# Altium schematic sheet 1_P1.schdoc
size 307 x 218 mm; Symbol: Drawing-Symbol_A4; Device: Drawing-Symbol_A4; @Project Name: Pixeldust-dr; @Page Count: 1; @Update Date: 2025-04-12; @Create Date: 2025-04-03; @Schematic Name: Schematic1; @Page No: 1; @Page Name: P1; Company: EasyEDA.com; Version: V1.0; Page Size: A4; @Create Time: 14:28:44; @Update Time: 18:55:47; Width: 1170; Height: 825; Region Start: 1; X Region Count: 6; Y Region Count: 4; Blade Width: 10; Title Block Position: 3; @Board Name: Board1
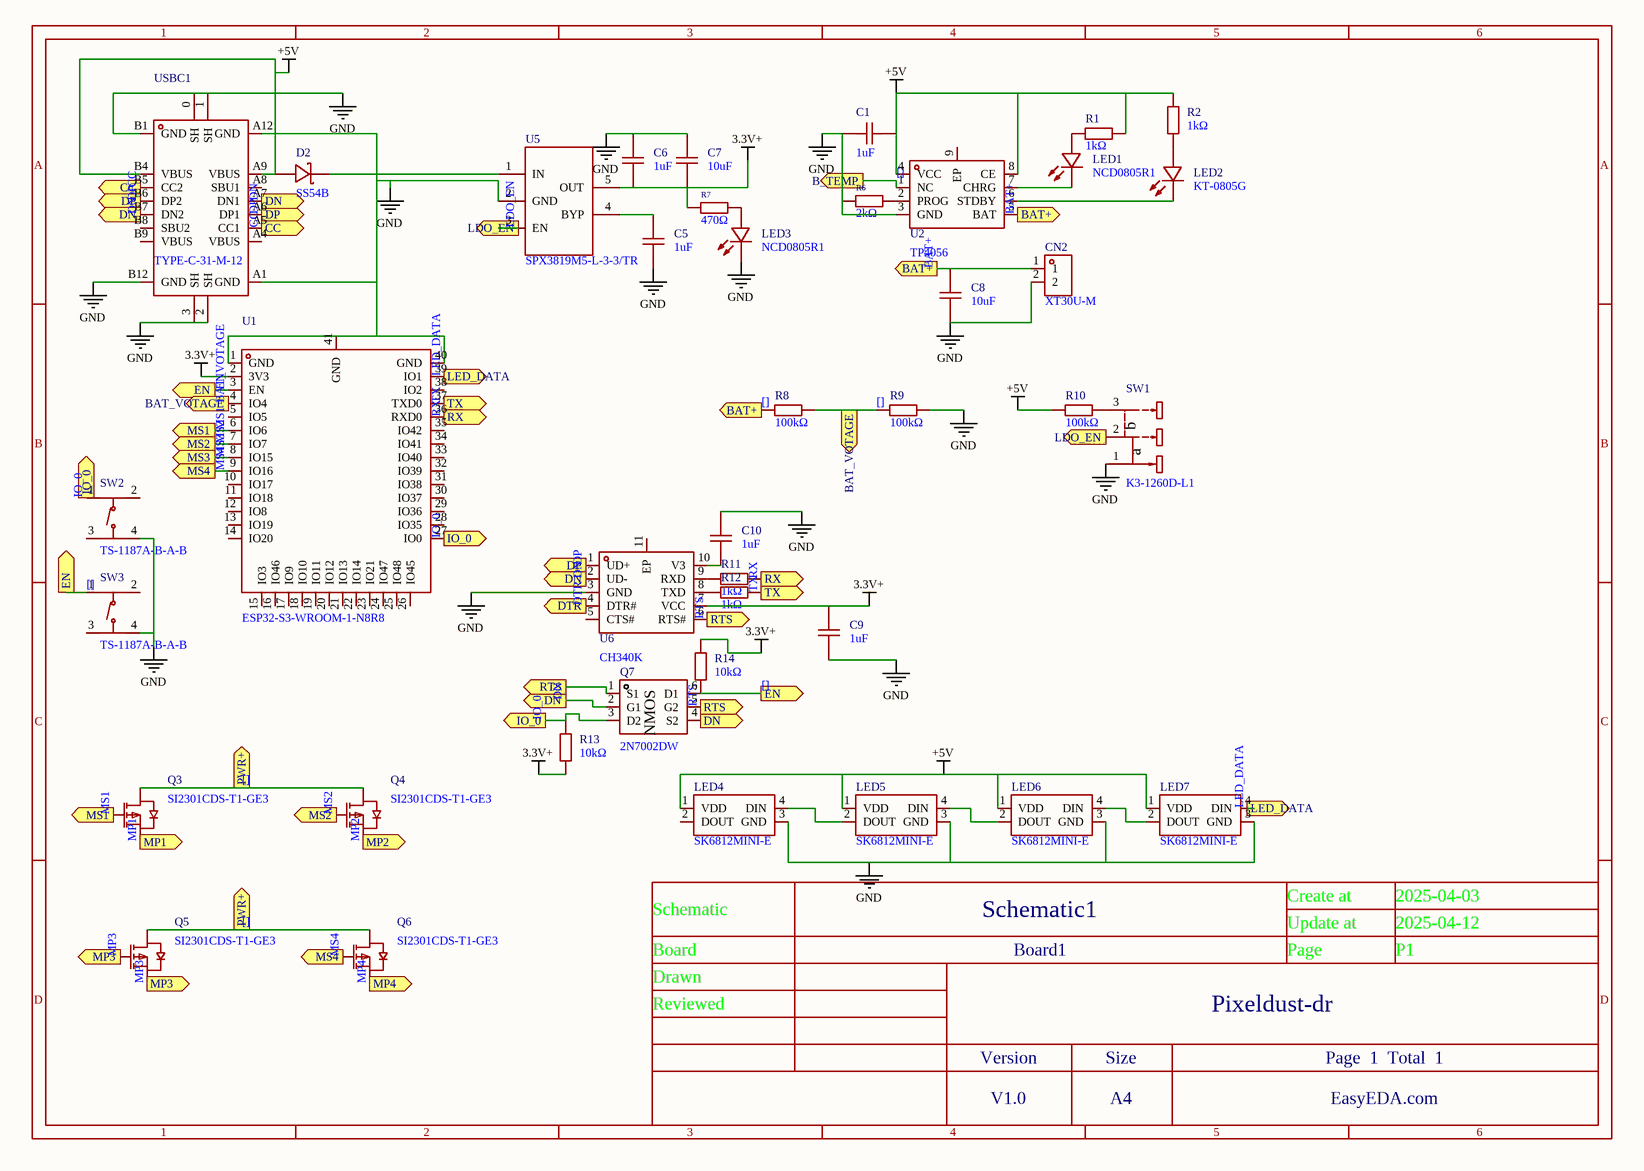
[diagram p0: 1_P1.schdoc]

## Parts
C1  1uF  [C0603]
C5  1uF  [C0603]
C6  1uF  [C0603]
C7  10uF  [C0603]
C8  10uF  [C0603]
C9  1uF  [C0603]
C10  1uF  [C0603]
CN2  XT30U-M  [CONN-TH_XT30U-M]
D2  SS54B  [SMB_L4.6-W3.6-LS5.3-RD]
LED1  NCD0805R1  [LED0805-R-RD]
LED2  KT-0805G  [LED0805-R-RD]
LED3  NCD0805R1  [LED0805-R-RD]
LED4  SK6812MINI-E  [LED-SMD_L3.2-W2.8-LS5.9_SK6812MINI-E]
LED5  SK6812MINI-E  [LED-SMD_L3.2-W2.8-LS5.9_SK6812MINI-E]
LED6  SK6812MINI-E  [LED-SMD_L3.2-W2.8-LS5.9_SK6812MINI-E]
LED7  SK6812MINI-E  [LED-SMD_L3.2-W2.8-LS5.9_SK6812MINI-E]
Q3  SI2301CDS-T1-GE3  [SOT-23-3_L3.0-W1.7-P0.95-LS2.9-BR]
Q4  SI2301CDS-T1-GE3  [SOT-23-3_L3.0-W1.7-P0.95-LS2.9-BR]
Q5  SI2301CDS-T1-GE3  [SOT-23-3_L3.0-W1.7-P0.95-LS2.9-BR]
Q6  SI2301CDS-T1-GE3  [SOT-23-3_L3.0-W1.7-P0.95-LS2.9-BR]
Q7  2N7002DW  [SOT-363_L2.0-W1.3-P0.65-LS2.1-BL]
R1  1kΩ  [R0603]
R2  1kΩ  [R0603]
R6  2kΩ  [R0805]
R7  470Ω  [R0805]
R8  100kΩ  [R1206]
R9  100kΩ  [R1206]
R10  100kΩ  [R1206]
R11  1kΩ  [R0603]
R12  1kΩ  [R0603]
R13  10kΩ  [R0805]
R14  10kΩ  [R0805]
SW1  K3-1260D-L1  [SW-TH_K3-1260D-L1]
SW2  TS-1187A-B-A-B  [SW-SMD_4P-L5.1-W5.1-P3.70-LS6.5-TL_H1.5]
SW3  TS-1187A-B-A-B  [SW-SMD_4P-L5.1-W5.1-P3.70-LS6.5-TL_H1.5]
U1  ESP32-S3-WROOM-1-N8R8  [WIRELM-SMD_ESP32-S3-WROOM-1]
U2  TP4056  [ESOP-8_L4.9-W3.9-P1.27-LS6.0-BL-EP-1]
U5  SPX3819M5-L-3-3/TR  [SOT-23-5_L3.0-W1.7-P0.95-LS2.8-BL]
U6  CH340K  [ESOP-10_L4.9-W3.9-P1.00-LS6.2-BL-EP]
USBC1  TYPE-C-31-M-12  [USB-C_SMD-TYPE-C-31-M-12]

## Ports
B_TEMP (out), BAT+ (out), BAT_VOTAGE (out), CC (out), DN (out), DP (out), DTR (out), EN (out), IO_0 (out), LDO_EN (out), LED_DATA (out), MP1 (out), MP2 (out), MP3 (out), MP4 (out), MS1 (out), MS2 (out), MS3 (out), MS4 (out), PWR+ (out), RTS (out), RX (out), TX (out)

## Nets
3.3V+: C6.2 C7.2 C9.1 R7.1 R13.1 R14.2 U1.2(3V3) U5.5(OUT) U6.7(VCC)
+5V: C1.1 D2.2(A) LED4.1(VDD) LED5.1(VDD) LED6.1(VDD) LED7.1(VDD) R1.1 R2.1 R10.2 U2.4(VCC) U2.8(CE) USBC1.A9(VBUS) USBC1.B4(VBUS)
GND: C1.2 C5.2 C6.1 C7.1 C8.2 C9.2 C10.1 CN2.2 LED3.2(-) LED4.3(GND) LED5.3(GND) LED6.3(GND) LED7.3(GND) R6.1 R9.2 SW1.1 SW2.4(D) SW3.4(D) U1.1(GND) U1.40(GND) U1.41(GND) U2.3(GND) U5.2(GND) U6.3(GND) USBC1.0(SH) USBC1.1(SH) USBC1.2(SH) USBC1.3(SH) USBC1.A1(GND) USBC1.A12(GND) USBC1.B1(GND) USBC1.B12(GND)
[]: C8.1 CN2.1 Q3.3(D) Q4.3(D) Q5.3(D) Q6.3(D) Q7.6(D1) R8.1 R8.2 R9.1 R14.1 SW3.1(A) U1.3(EN) U1.4(IO4) U2.1(NC) U2.5(BAT) ; port BAT+, port B_TEMP, port PWR+, port BAT_VOTAGE, port EN  [also labelled BAT+, BAT_VOTAGE, EN]
CC: USBC1.A5(CC1) USBC1.B5(CC2) ; port CC
DN: Q7.2(G1) Q7.4(S2) U6.2(UD-) USBC1.A7(DN1) USBC1.B7(DN2) ; port DN
DP: U6.1(UD+) USBC1.A6(DP1) USBC1.B6(DP2) ; port DP
DTR: U6.4(DTR#) ; port DTR
IO_0: Q7.3(D2) R13.2 SW2.1(A) U1.27(IO0) ; port IO_0
LDO_EN: SW1.2 U5.3(EN) ; port LDO_EN
LED_DATA: LED7.4(DIN) U1.39(IO1) ; port LED_DATA
MP1: Q3.2(S) ; port MP1
MP2: Q4.2(S) ; port MP2
MP3: Q5.1(G) Q5.2(S) ; port MP3
MP4: Q6.2(S) ; port MP4
MS1: Q3.1(G) U1.6(IO6) ; port MS1
MS2: Q4.1(G) U1.7(IO7) ; port MS2
MS3: U1.8(IO15) ; port MS3
MS4: Q6.1(G) U1.9(IO16) ; port MS4
RTS: Q7.1(S1) Q7.5(G2) U6.6(RTS#) ; port RTS
RX: R11.1 U1.36(RXD0) ; port RX
TX: R12.1 U1.37(TXD0) ; port TX
NetC5_1: C5.1 U5.4(BYP)
NetC10_2: C10.2 U6.10(V3)
NetD2_1: D2.1(K) U5.1(IN)
NetLED1_1: LED1.1(+) R1.2
NetLED1_2: LED1.2(-) U2.7(CHRG)
NetLED2_1: LED2.1(A) R2.2
NetLED2_2: LED2.2(K) U2.6(STDBY)
NetLED3_1: LED3.1(+) R7.2
NetLED4_4: LED4.4(DIN) LED5.2(DOUT)
NetLED5_4: LED5.4(DIN) LED6.2(DOUT)
NetLED6_4: LED6.4(DIN) LED7.2(DOUT)
NetR6_2: R6.2 U2.2(PROG)
NetR10_1: R10.1 SW1.3
NetR11_2: R11.2 U6.9(RXD)
NetR12_2: R12.2 U6.8(TXD)

Not connected (* = marked no-connect by the designer): LED4 2(DOUT); SW2 2(B) 3(C); SW3 2(B) 3(C); U1 5(IO5) 10(IO17) 11(IO18) 12(IO8) 13(IO19) 14(IO20) 15(IO3) 16(IO46) 17(IO9) 18(IO10) 19(IO11) 20(IO12) 21(IO13) 22(IO14) 23(IO21) 24(IO47) 25(IO48) 26(IO45) 28(IO35) 29(IO36) 30(IO37) 31(IO38) 32(IO39) 33(IO40) 34(IO41) 35(IO42) 38(IO2); U2 9(EP); U6 5(CTS#) 11(EP); USBC1 A4(VBUS) A8(SBU1) B8(SBU2) B9(VBUS)

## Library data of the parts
C1 C5 C6 C9 C10 = CL10A105KB8NNNC: Manufacturer: SAMSUNG(三星); Add into BOM: yes; Tolerance: ±10%
C7 C8 = CL10A106KP8NNNC: Manufacturer: SAMSUNG(三星); Add into BOM: yes; Tolerance: ±10%
CN2 = XT30U-M: Manufacturer: AMASS(艾迈斯); Add into BOM: yes; Brand: 艾迈斯; InterfaceType: 公头
D2 = SS54B_C32513: Manufacturer: MDD(辰达半导体); Symbol: SS54; Add into BOM: yes; Diode Configuration: Independent Type; Forward Voltage (Vf@If): 550mV@5A; Reverse Voltage (Vr): 40V; Rectified Current: 5A; Reverse Leakage Current (Ir): 1mA@40V
LED1 LED3 = NCD0805R1_C84256: Manufacturer: 国星光电; Symbol: FC-2012HRK-620D; Add into BOM: yes; Emitted Color: Red; Forward Voltage (VF): 1.6V~2.6V; Power Dissipation: 65mW; Forward Current: 20mA; Dominant Wavelength: 615nm~630nm; Diode Configuration: 独立二极管; Lens Color: 无色透明透镜; Luminous Intensity: 67mcd~195mcd; Viewing Angle: 130°
LED2 = KT-0805G: Manufacturer: KENTO; Symbol: 0805G (Green); Add into BOM: yes; Emitted Color: Emerald
LED4-LED7 = SK6812MINI-E_C5149201: Manufacturer: 欧思科光电; Add into BOM: yes
Q3-Q6 = SI2301CDS-T1-GE3: Manufacturer: VISHAY(威世); Add into BOM: yes; Type: 1 Piece P-Channel; Drain Source On Resistance (RDS(on)@Vgs,Id): 0.112Ω@4.5V,2.8A; Power Dissipation (Pd): 0.86W; Gate Threshold Voltage (Vgs(th)@Id): 1V@250uA; Total Gate Charge (Qg@Vgs): 3.3nC@10V; Input Capacitance (Ciss@Vds): 405pF@10V; Reverse Transfer Capacitance (Crss@Vds): 55pF@10V
Q7 = 2N7002DW_C699281: Manufacturer: YANGJIE(扬杰); Add into BOM: yes; Type: 2 N-Channel; Drain to Source Voltage: 60V; Current - Continuous Drain(Id): 340mA; RDS(on): 1.2Ω@10V,300mA; Gate Threshold Voltage (Vgs(th)@Id): 2.5V; Gate Charge(Qg): 1.7nC@15V; Reverse Transfer Capacitance (Crss@Vds): 5.5pF@30V
R1 R2 R11 R12 = RC0603JR-071KL: Manufacturer: YAGEO(国巨); Add into BOM: yes; Tolerance: ±5%; Temperature Coefficient: ±100ppm/℃
R6 = 0805W8F2001T5E: Manufacturer: UNI-ROYAL(厚声); Add into BOM: yes; Tolerance: ±1%; Temperature Coefficient: ±100ppm/℃
R7 = 0805W8F4700T5E: Manufacturer: UNI-ROYAL(厚声); Add into BOM: yes; Tolerance: ±1%; Temperature Coefficient: ±100ppm/℃
R8-R10 = 1206W4F1003T5E: Manufacturer: UNI-ROYAL(厚声); Add into BOM: yes; Tolerance: ±1%; Temperature Coefficient: ±100ppm/℃
R13 R14 = 0805W8F1002T5E: Manufacturer: UNI-ROYAL(厚声); Add into BOM: yes; Tolerance: ±1%; Temperature Coefficient: ±100ppm/℃
SW1 = K3-1260D-L1: Manufacturer: 韩国韩荣; Add into BOM: yes; Circuit: SPDT; Actuator Style: Rectangular columnar; Pin Style: PCPin; Switch Length: 9mm; Switch Width: 3.5mm; Actuator Color: Black; Current Rating (DC): 300mA; Voltage Rating (DC): 6V; Mechanical Life: 1万次
SW2 SW3 = TS-1187A-B-A-B: Manufacturer: XKB Connectivity(中国星坤); Add into BOM: yes; Circuit: SPST; Actuator Style: Round Button; Operating Force: 160gf; Switch Length: 5.1mm; Switch Height: 1.5mm; Strike Gundam: 不带; Contact Current: 50mA; Voltage Rating (DC): 12V; Actuator/Cap Color: 金色; With Lamp: No; Mechanical Life: 10万次
U1 = ESP32-S3-WROOM-1-N8R8: Manufacturer: ESPRESSIF(乐鑫); Symbol: ESP32-S3-WROOM-1(N8R8); Add into BOM: yes
U2 = TP4056_C17702041: Manufacturer: HXY MOSFET(华轩阳电子); Add into BOM: yes; Supply Voltage: 4.5V~8V; Maximum Charge Current: 1.2A; Type of Battery: Lithium-ion; Number of Cells: 1
U5 = SPX3819M5-L-3-3/TR: Manufacturer: MaxLinear(迈凌); Add into BOM: yes; Output Type: Fixed; Maximum Input Voltage: 16V; Output Voltage: 3.3V; Output Current: 500mA; Power Supply Rejection Ratio (PSRR): 70dB; Dropout Voltage: 700mV@(500mA); standby current: 8uA; Output Polarity: Positive electrode; Number of Outputs: 1
U6 = CH340K: Manufacturer: WCH(南京沁恒); Add into BOM: yes; Applications Function: USB to serial; Supply Voltage: 3.3V；5V; Data Rate: 2Mbps
USBC1 = TYPE-C-31-M-12: Manufacturer: 韩国韩荣; Add into BOM: yes; Connector Type: Type-C; Gender: Female; Number of Contacts: 16P; Number of Ports: 1; Current Rating - Power (Max): 5A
